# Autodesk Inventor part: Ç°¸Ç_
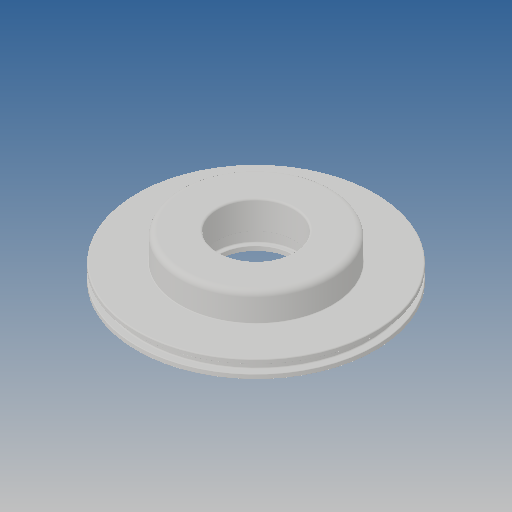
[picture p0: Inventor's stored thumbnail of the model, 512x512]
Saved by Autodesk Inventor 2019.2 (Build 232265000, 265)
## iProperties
Created: 2013-07
Part Number: Ç°¸Ç_
Material: Ogólny
Document SubType Name: Modeling
Designer: CADENGINEERING4
Density: 1 g/cm^3
Appearance: Domyślna
Author: CADENGINEERING4
Revision Number: ÈÎºÎ
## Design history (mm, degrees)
feature "Ðý×ª1"
node "Bryła1"
